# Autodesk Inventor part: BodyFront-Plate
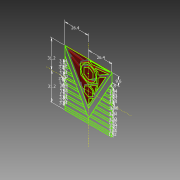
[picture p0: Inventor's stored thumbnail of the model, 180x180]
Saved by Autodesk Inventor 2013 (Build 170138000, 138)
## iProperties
Created: 2013-04
Part Number: BodyFront-Plate
Material: Generic
Document SubType Name: Modeling
Designer: frankenteddy
Density: 1 g/cm^3
Author: frankenteddy
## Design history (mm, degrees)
sketch "Sketch1"
  geometry: L1 (0, -5.333)-(-4.619, -2.667); L2 (0, -16.309)-(26.4, 31.2); L3 (26.4, 31.2)-(-26.4, 31.2); L4 (26.4, 31.2)-(-26.4, 31.2); L5 (26.4, 31.2)-(26.4, -31.2); L6 (-26.4, -27.36)-(26.4, -27.36); L7 (-26.4, -29.28)-(26.4, -29.28); L8 (-26.4, -31.2)-(26.4, -31.2); L9 (-26.4, -31.2)-(26.4, -31.2); L10 (-26.4, 31.2)-(0, -16.309); L11 (-26.4, -31.2)-(-26.4, 31.2); L12 (4.619, -2.667)-(0, -5.333); L13 (-0.575, -6.754)-(-5.345, -4); L14 (-5.345, -4)-(-0.575, -12.583); L15 (-0.575, -12.583)-(-0.575, -6.754); L16 (5.595, -15.84)-(26.4, -15.84); L17 (4.528, -17.76)-(26.4, -17.76); L18 (1.327, -23.52)-(26.4, -23.52); L19 (2.394, -21.6)-(26.4, -21.6); L20 (4.619, 2.667)-(4.619, -2.667); L21 (0, 5.333)-(4.619, 2.667); L22 (-4.619, 2.667)-(0, 5.333); L23 (-5.802, 3.865)-(-1.821, 6.076); L24 (9.104, 12.135)-(0, 6.879); L25 (0, 6.879)-(-9.104, 12.135); L26 (-4.619, -2.667)-(-4.619, 2.667); L27 (9.104, 22.647)-(9.104, 12.135); L28 (-19.363, 23.277)-(-8.868, 4.391); L29 (-26.4, 31.2)-(-26.4, 21.6); L30 (-9.104, 12.135)-(-9.104, 22.647); L31 (-9.104, 22.647)-(0, 27.903); L32 (-10.6, 12.135)-(-10.6, 18.218); L33 (-10.6, 20.938)-(-10.6, 23.926); L34 (-10.6, 23.926)-(-7.135, 25.926); L35 (-4.062, 27.88)-(-1.427, 30.402); L36 (-10.6, 18.218)-(-19.363, 23.277); L37 (-1.427, 30.402)-(-23.872, 30.402); L38 (-23.872, 30.402)-(-4.062, 27.88); L39 (-7.135, 25.926)-(-22.663, 27.903); L40 (-22.663, 27.903)-(-10.6, 20.938); L41 (-5.802, 0)-(-5.802, 3.865); L42 (-8.868, 10.145)-(-7.135, 2.4); L43 (-8.868, 4.391)-(-10.6, 12.135); L44 (-7.135, 2.4)-(-5.802, 0); L45 (-26.4, 12.96)-(-21.599, 12.96); L46 (-26.4, 16.8)-(-23.733, 16.8); L47 (-1.821, 6.076)-(-8.868, 10.145); L48 (0, 27.903)-(9.104, 22.647); L49 (-5.097, 14.448)-(-5.097, 20.334); L50 (-5.097, 20.334)-(0, 23.277); L51 (0, 11.505)-(-5.097, 14.448); L52 (0, 23.277)-(5.097, 20.334); L53 (5.097, 20.334)-(5.097, 14.448); L54 (5.097, 14.448)-(0, 11.505); L55 (-26.4, 11.04)-(-20.532, 11.04); L56 (-26.4, -6.24)-(-10.93, -6.24); L57 (-26.4, -4.32)-(-11.997, -4.32); L58 (-26.4, -0.48)-(-14.13, -0.48); L59 (-26.4, 1.44)-(-15.197, 1.44); L60 (-26.4, 5.28)-(-17.331, 5.28); L61 (-26.4, 7.2)-(-18.398, 7.2); L62 (-26.4, -10.08)-(-8.796, -10.08); L63 (-26.4, -15.84)-(-5.595, -15.84); L64 (-26.4, -17.76)-(-4.528, -17.76)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; C1 r 8.289 at (0, 17.391); 5 further points
  constraints: 162 end point, 33 parallel, 11 perpendicular, 7 horizontal, 4 point on line, 2 coincident, 2 collinear, 1 centre point, 116 other
  dimensions: "d0" = 9.6 distance of L3.end L29.end; "d1" = 4.8 distance from line of L29.end L46; "d2" = 3.84 distance between parallel lines of L45 L46; "d3" = 1.92 distance between parallel lines of L55 L45; "d4" = 3.84 distance between parallel lines of L61 L55; "d5" = 1.92 distance between parallel lines of L60 L61; "d6" = 3.84 distance between parallel lines of L59 L60; "d7" = 1.92 distance between parallel lines of L58 L59; "d8" = 3.84 distance between parallel lines of L57 L58; "d9" = 1.92 distance between parallel lines of L56 L57; "d10" = 3.84 distance between parallel lines of L62 L56; "d11" = 1.92 distance between parallel lines of L67 L62; "d12" = 3.84 distance between parallel lines of L63 L67; "d13" = 1.92 distance between parallel lines of L64 L63; "d14" = 3.84 distance between parallel lines of L65 L64; "d15" = 1.92 distance between parallel lines of L66 L65; "d16" = 3.84 distance between parallel lines of L6 L66; "d17" = 1.92 distance between parallel lines of L7 L6; "d18" = 3.84 distance between parallel lines of L18 L6; "d19" = 1.92 distance between parallel lines of L18 L19; "d20" = 3.84 distance between parallel lines of L19 L17; "d21" = 1.92 distance between parallel lines of L17 L16; "d22" = 3.84 distance between parallel lines of L16 L73; "d23" = 1.92 distance between parallel lines of L73 L68; "d24" = 3.84 distance between parallel lines of L68 L69; "d25" = 1.92 distance between parallel lines of L69 L70; "d26" = 3.84 distance between parallel lines of L70 L71; "d27" = 1.92 distance between parallel lines of L71 L72; "d28" = 3.84 distance between parallel lines of L72 L75; "d29" = 1.92 distance between parallel lines of L75 L76; "d30" = 3.84 distance between parallel lines of L76 L77; "d31" = 1.92 distance between parallel lines of L77 L79; "d32" = 3.84 distance between parallel lines of L79 L78; "d33" = 31.2 distance between parallel lines of L80 L3; "d34" = 26.4 distance between parallel lines of L81 L5; "d35" = 26.4 distance between parallel lines of L11 L81; "d36" = 31.2 distance between parallel lines of L80 L8
extrude "Extrusion5" new body sketch "Sketch1" distance "d47" = 3; taper "d48" = 0 deg
extrude "Extrusion6" new body sketch "Sketch1" distance "d49" = 1.5; taper "d50" = 0 deg
mirror "Mirror2"
body "Solid1"
body "Solid2"
body "Solid3"
